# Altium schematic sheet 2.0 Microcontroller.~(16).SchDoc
size A4; SheetNumber: 2; SheetTotal: 7
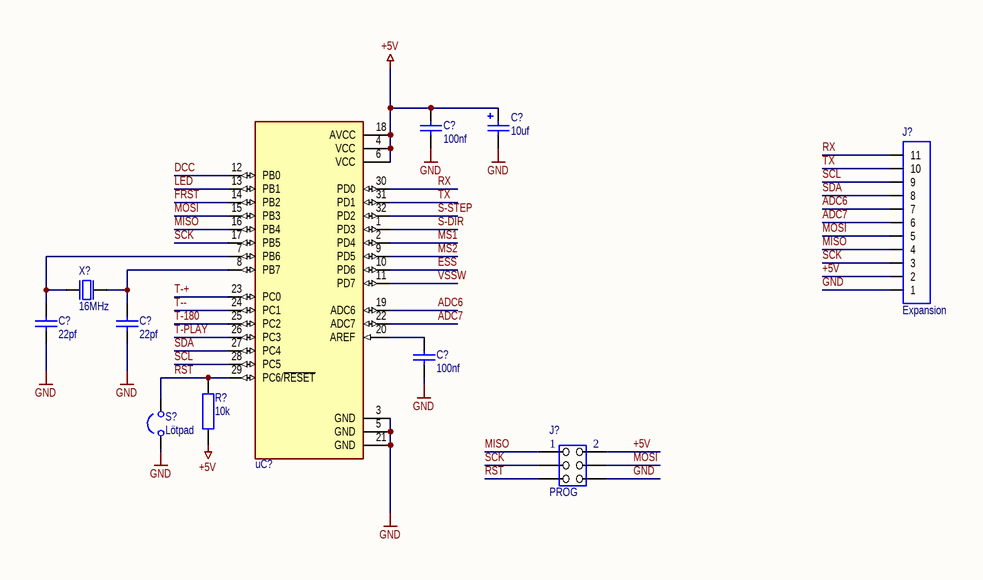
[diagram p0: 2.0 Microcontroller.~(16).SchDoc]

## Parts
(Parts that share a designator on the sheet are numbered #1, #2 ... from top to bottom, then left to right.)
C?#1  10uf  [C_SMD_C-TYP]
C?#2  100nf  [C_SMD_0805]
C?#3  22pf  [C_SMD_0805]
C?#4  22pf  [C_SMD_0805]
C?#5  100nf  [C_SMD_0805]
J?#1  Expansion  [SIP-11]
J?#2  PROG  [J_2x3]
R?  10k  [R_SMD_0805]
S?  Lötpad  [S_SMD_Pad-NO]
uC?  ATMega328(p)-AU  [TQFP-32]  (value not drawn)
X?  16MHz  [X_SMD_XTAL]

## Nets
+5V: C?#1.1 C?#2.1 J?#1.2 J?#2.2 R?.1 uC?.4(VCC) uC?.6(VCC) uC?.18(AVCC)
GND: C?#1.2 C?#2.2 C?#3.2 C?#4.2 C?#5.2 J?#1.1 J?#2.6 S?.1 uC?.3(GND) uC?.5(GND) uC?.21(GND)
ADC6: J?#1.7 uC?.19(ADC6)
ADC7: J?#1.6 uC?.22(ADC7)
DCC: uC?.12(PB0)
ESS: uC?.10(PD6)
FRST: uC?.14(PB2)
LED: uC?.13(PB1)
MISO: J?#1.4 J?#2.1 uC?.16(PB4)
MOSI: J?#1.5 J?#2.4 uC?.15(PB3)
MS1: uC?.2(PD4)
MS2: uC?.9(PD5)
RST: J?#2.5 R?.2 S?.2 uC?.29(PC6/~{RESET})
RX: J?#1.11 uC?.30(PD0)
S-DIR: uC?.1(PD3)
S-STEP: uC?.32(PD2)
SCK: J?#1.3 J?#2.3 uC?.17(PB5)
SCL: J?#1.9 uC?.28(PC5)
SDA: J?#1.8 uC?.27(PC4)
T-180: uC?.25(PC2)
T-+: uC?.23(PC0)
T--: uC?.24(PC1)
T-PLAY: uC?.26(PC3)
TX: J?#1.10 uC?.31(PD1)
VSSW: uC?.11(PD7)
NetC?#3_1: C?#3.1 uC?.7(PB6) X?.1
NetC?#4_1: C?#4.1 uC?.8(PB7) X?.2
NetC?#5_1: C?#5.1 uC?.20(AREF)

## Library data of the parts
C?#1 = C_SMD_ELK: SMD Elektrolytkondensator
C?#2-C?#5 = C_SMD_KO: Kondensator SMD Universal, Keramik, Folie, usw.
J?#1 = J_THT_CON11: Stecker
J?#2 = J_THT_IDC 2x3: Stecker
R? = R_SMD_Widerstand: Widerstand SMD
S? = S_SMD_Jumper: Lötverbinder
uC? = UC_ATMega328P-AU: Microcontroller
X? = X_SMD_Quarz: Quarz SMD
